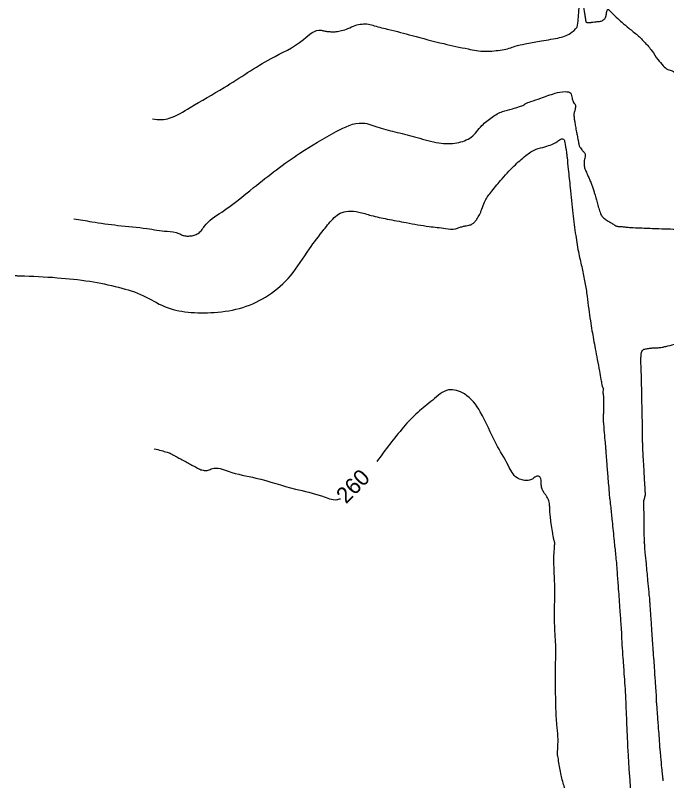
# Model space of a CAD drawing. Extents: x -475575 to -473225, y -1116053 to -1114104.
# Drawn here: x -475562.3 to -475400.4, y -1115778.9 to -1115588.6 of the extents above; entities that cross this region are included whole.
import ezdxf

# ---------------------------------------------------------------- set-up
doc = ezdxf.new("R2010")
doc.units = 0
for name, color, linetype in [('Vrstevnice_hlavni', 7, 'Continuous'), ('Vrstevnice_popis', 7, 'Continuous'), ('Vrstevnice_vedlejsi', 7, 'Continuous')]:
    doc.layers.add(name, color=color, linetype=linetype)

msp = doc.modelspace()

# ---------------------------------------------------------------- linework, layer by layer
at = {"layer": 'Vrstevnice_hlavni'}
for points in [[(-475427.48600000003, -1115772.132), (-475427.49100000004, -1115772.047), (-475427.47500000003, -1115771.565), (-475427.43600000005, -1115770.685), (-475427.37600000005, -1115769.409), (-475427.39, -1115768.06), (-475427.48000000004, -1115766.6400000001), (-475427.645, -1115765.148), (-475427.76700000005, -1115763.73), (-475427.847, -1115762.387), (-475427.884, -1115761.118), (-475427.927, -1115759.2580000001), (-475427.978, -1115756.807), (-475428.03400000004, -1115753.7650000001), (-475428.041, -1115751.345), (-475427.99600000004, -1115749.547), (-475427.901, -1115748.371), (-475427.895, -1115746.679), (-475427.977, -1115744.47), (-475428.14900000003, -1115741.745), (-475428.24100000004, -1115739.05), (-475428.25200000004, -1115736.386), (-475428.184, -1115733.7510000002), (-475428.178, -1115731.1800000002), (-475428.234, -1115728.672), (-475428.353, -1115726.2280000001), (-475428.39300000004, -1115724.148), (-475428.35500000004, -1115722.4340000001), (-475428.24000000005, -1115721.083), (-475428.199, -1115720.101), (-475428.233, -1115719.4880000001), (-475428.342, -1115719.242), (-475428.51700000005, -1115718.399), (-475428.759, -1115716.959), (-475429.06700000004, -1115714.922), (-475429.283, -1115713.216), (-475429.408, -1115711.841), (-475429.44100000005, -1115710.798), (-475429.52400000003, -1115709.952), (-475429.657, -1115709.3050000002), (-475429.83900000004, -1115708.855), (-475430.12700000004, -1115708.324), (-475430.521, -1115707.712), (-475431.021, -1115707.017), (-475431.37200000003, -1115706.139), (-475431.574, -1115705.077), (-475431.628, -1115703.831), (-475432.03900000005, -1115703.232), (-475432.808, -1115703.28), (-475433.934, -1115703.976), (-475435.102, -1115704.2580000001), (-475436.31200000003, -1115704.127), (-475437.563, -1115703.583), (-475439.711, -1115700.578), (-475442.75700000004, -1115695.111), (-475446.7, -1115687.183), (-475450.641, -1115682.727), (-475454.581, -1115681.744), (-475458.52, -1115684.232), (-475462.25200000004, -1115687.314), (-475465.77800000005, -1115690.989), (-475472.417, -1115699.5250000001)], [(-475527.74600000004, -1115696.3490000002), (-475525.965, -1115696.8020000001), (-475524.571, -1115697.22), (-475523.56600000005, -1115697.601), (-475522.949, -1115697.946), (-475522.123, -1115698.398), (-475521.08900000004, -1115698.9570000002), (-475519.847, -1115699.6230000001), (-475518.65300000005, -1115700.264), (-475517.50700000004, -1115700.879), (-475516.41000000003, -1115701.468), (-475515.34400000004, -1115701.734), (-475514.309, -1115701.6770000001), (-475513.304, -1115701.2950000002), (-475509.358, -1115701.952), (-475502.46900000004, -1115703.646), (-475492.639, -1115706.378), (-475485.938, -1115708.164), (-475482.367, -1115709.002), (-475481.483, -1115708.786)], [(-475432.54600000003, -1115864.7240000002), (-475432.438, -1115866.5180000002), (-475432.42000000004, -1115867.2), (-475432.43600000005, -1115867.668), (-475432.488, -1115867.922), (-475432.49700000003, -1115868.151), (-475432.465, -1115868.355), (-475432.391, -1115868.534), (-475432.05500000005, -1115868.639), (-475431.456, -1115868.671), (-475430.59500000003, -1115868.629), (-475429.677, -1115868.433), (-475428.70200000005, -1115868.084), (-475427.67000000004, -1115867.581), (-475426.97000000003, -1115867.2380000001), (-475426.602, -1115867.057), (-475426.56600000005, -1115867.0350000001), (-475426.31600000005, -1115866.919), (-475425.85400000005, -1115866.706), (-475425.178, -1115866.398), (-475424.803, -1115865.685), (-475424.72900000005, -1115864.568), (-475424.955, -1115863.047), (-475424.634, -1115861.753), (-475423.764, -1115860.686), (-475422.34500000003, -1115859.8460000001), (-475421.254, -1115858.935), (-475420.49100000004, -1115857.9540000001), (-475420.05500000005, -1115856.9030000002), (-475419.68600000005, -1115856.084), (-475419.38200000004, -1115855.4980000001), (-475419.145, -1115855.1430000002), (-475418.961, -1115854.685), (-475418.831, -1115854.122), (-475418.755, -1115853.455), (-475418.75800000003, -1115851.736), (-475418.842, -1115848.962), (-475419.005, -1115845.136), (-475419.118, -1115842.469), (-475419.18000000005, -1115840.9610000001), (-475419.193, -1115840.612), (-475419.22900000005, -1115840.026), (-475419.291, -1115839.203), (-475419.37600000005, -1115838.142), (-475419.465, -1115836.504), (-475419.558, -1115834.288), (-475419.655, -1115831.494), (-475419.75, -1115829.593), (-475419.846, -1115828.587), (-475419.94, -1115828.4740000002), (-475420.16500000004, -1115827.6430000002), (-475420.522, -1115826.095), (-475421.01, -1115823.827), (-475421.44700000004, -1115821.397), (-475421.83400000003, -1115818.8020000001), (-475422.17100000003, -1115816.043), (-475422.433, -1115813.953), (-475422.62, -1115812.529), (-475422.732, -1115811.774), (-475422.786, -1115811.155), (-475422.781, -1115810.672), (-475422.71800000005, -1115810.3260000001), (-475422.907, -1115809.202), (-475423.34900000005, -1115807.299), (-475424.044, -1115804.619), (-475424.51300000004, -1115802.821), (-475424.756, -1115801.905), (-475424.77300000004, -1115801.872), (-475424.776, -1115801.469), (-475424.76300000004, -1115800.698), (-475424.737, -1115799.557), (-475424.70800000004, -1115798.28), (-475424.678, -1115796.867), (-475424.647, -1115795.318), (-475424.635, -1115793.85), (-475424.64400000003, -1115792.463), (-475424.673, -1115791.158), (-475424.722, -1115789.6060000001), (-475424.79000000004, -1115787.807), (-475424.879, -1115785.761), (-475424.95800000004, -1115784.2410000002), (-475425.027, -1115783.247), (-475425.087, -1115782.779), (-475425.14, -1115782.441), (-475425.185, -1115782.234), (-475425.22400000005, -1115782.1570000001), (-475425.408, -1115781.607), (-475425.738, -1115780.5860000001), (-475426.21400000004, -1115779.092), (-475426.62, -1115777.5010000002), (-475426.956, -1115775.813), (-475427.222, -1115774.0280000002), (-475427.39900000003, -1115772.8360000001), (-475427.48600000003, -1115772.235), (-475427.483, -1115772.226), (-475427.483, -1115772.192), (-475427.48600000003, -1115772.132)]]:
    msp.add_spline(points, degree=3, dxfattribs=at)
at = {"layer": 'Vrstevnice_vedlejsi'}
for points in [[(-475422.59400000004, -1115591.47), (-475422.356, -1115589.511), (-475422.178, -1115587.384), (-475422.06200000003, -1115585.0890000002), (-475422.006, -1115582.625), (-475421.824, -1115581.962), (-475421.514, -1115583.1), (-475421.07800000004, -1115586.04), (-475420.77300000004, -1115588.0860000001), (-475420.59900000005, -1115589.2410000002), (-475420.55600000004, -1115589.504), (-475420.521, -1115589.732), (-475420.494, -1115589.9270000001), (-475420.473, -1115590.087), (-475420.43700000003, -1115590.202), (-475420.385, -1115590.271), (-475420.318, -1115590.2950000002), (-475420.16000000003, -1115590.313), (-475419.91400000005, -1115590.327), (-475419.57800000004, -1115590.335), (-475419.331, -1115590.331), (-475419.174, -1115590.314), (-475419.106, -1115590.2850000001), (-475418.69200000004, -1115590.23), (-475417.934, -1115590.149), (-475416.83, -1115590.0420000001), (-475416.03400000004, -1115589.681), (-475415.54600000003, -1115589.065), (-475415.36500000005, -1115588.193), (-475415.215, -1115587.574), (-475415.09500000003, -1115587.2070000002), (-475415.005, -1115587.091), (-475414.608, -1115587.357), (-475413.902, -1115588.003), (-475412.88800000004, -1115589.03), (-475411.506, -1115590.289), (-475409.756, -1115591.78), (-475407.63800000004, -1115593.503), (-475405.73500000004, -1115595.372), (-475404.04600000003, -1115597.384), (-475402.571, -1115599.5420000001), (-475401.24100000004, -1115601.088), (-475400.054, -1115602.024), (-475399.011, -1115602.348), (-475397.672, -1115603.344), (-475396.037, -1115605.011), (-475394.107, -1115607.351), (-475392.14800000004, -1115609.598), (-475390.16000000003, -1115611.752), (-475388.145, -1115613.814), (-475386.76, -1115615.574), (-475386.006, -1115617.033), (-475385.884, -1115618.19), (-475385.238, -1115619.1160000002), (-475384.068, -1115619.811), (-475382.375, -1115620.276), (-475380.439, -1115621.279), (-475378.26200000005, -1115622.82), (-475375.84300000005, -1115624.9000000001), (-475373.658, -1115626.291), (-475371.70800000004, -1115626.995), (-475369.992, -1115627.01), (-475368.27, -1115626.7680000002), (-475366.544, -1115626.266), (-475364.81200000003, -1115625.506), (-475363.342, -1115625.334), (-475362.135, -1115625.7480000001), (-475361.19100000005, -1115626.749), (-475360.489, -1115627.4440000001), (-475360.02800000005, -1115627.831), (-475359.809, -1115627.911), (-475359.51800000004, -1115627.955), (-475359.15300000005, -1115627.963), (-475358.716, -1115627.935), (-475358.223, -1115627.602), (-475357.674, -1115626.963), (-475357.068, -1115626.019), (-475356.50200000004, -1115625.144), (-475355.97500000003, -1115624.3390000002), (-475355.488, -1115623.602), (-475354.933, -1115623.111), (-475354.31, -1115622.867), (-475353.619, -1115622.869), (-475352.982, -1115622.911), (-475352.39800000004, -1115622.9910000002), (-475351.869, -1115623.111), (-475351.357, -1115623.2280000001), (-475350.86500000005, -1115623.342), (-475350.391, -1115623.452), (-475349.90300000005, -1115623.344), (-475349.402, -1115623.0180000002), (-475348.88700000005, -1115622.4740000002), (-475348.325, -1115622.057), (-475347.71400000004, -1115621.7680000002), (-475347.05500000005, -1115621.6060000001), (-475345.527, -1115620.777), (-475343.131, -1115619.281)], [(-475528.15173670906, -1115614.3358564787), (-475525.906, -1115614.49), (-475523.99600000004, -1115614.136), (-475518.82200000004, -1115611.487), (-475510.384, -1115606.5420000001), (-475498.68100000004, -1115599.3), (-475490.629, -1115594.539), (-475486.226, -1115592.256), (-475485.47400000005, -1115592.453), (-475484.60500000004, -1115592.58), (-475483.62100000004, -1115592.637), (-475482.52, -1115592.6230000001), (-475481.18200000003, -1115592.361), (-475479.60500000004, -1115591.851), (-475477.78900000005, -1115591.092), (-475476.08900000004, -1115590.72), (-475474.505, -1115590.735), (-475473.036, -1115591.136), (-475469.422, -1115592.0820000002), (-475463.66400000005, -1115593.573), (-475455.76, -1115595.609), (-475449.722, -1115596.923), (-475445.549, -1115597.5150000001), (-475443.243, -1115597.385), (-475441.22400000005, -1115597.132), (-475439.492, -1115596.757), (-475438.049, -1115596.2580000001), (-475435.55700000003, -1115595.6670000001), (-475432.015, -1115594.983), (-475427.423, -1115594.206), (-475424.283, -1115593.0350000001), (-475422.59400000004, -1115591.47)], [(-475547.69399277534, -1115639.1499769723), (-475543.27800000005, -1115639.8900000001), (-475536.754, -1115640.798), (-475529.574, -1115641.5960000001), (-475524.521, -1115642.264), (-475521.596, -1115642.804), (-475520.798, -1115643.215), (-475519.9, -1115643.426), (-475518.90300000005, -1115643.438), (-475517.80600000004, -1115643.249), (-475516.836, -1115642.783), (-475515.993, -1115642.04), (-475515.277, -1115641.02), (-475510.95900000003, -1115637.477), (-475503.04000000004, -1115631.4100000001), (-475491.52, -1115622.82), (-475482.48600000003, -1115617.466), (-475475.93700000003, -1115615.348), (-475471.875, -1115616.466), (-475467.362, -1115617.665), (-475462.4, -1115618.945), (-475456.988, -1115620.3050000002), (-475452.504, -1115620.267), (-475448.94700000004, -1115618.83), (-475446.31700000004, -1115615.995), (-475443.734, -1115613.878), (-475441.19800000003, -1115612.48), (-475438.70800000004, -1115611.8), (-475436.939, -1115611.26), (-475435.88800000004, -1115610.862), (-475435.558, -1115610.604), (-475434.14800000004, -1115610.0320000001), (-475431.658, -1115609.147), (-475428.09, -1115607.949), (-475425.60500000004, -1115607.546), (-475424.205, -1115607.939), (-475423.88800000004, -1115609.128), (-475423.612, -1115609.968), (-475423.37700000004, -1115610.46), (-475423.183, -1115610.6030000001), (-475423.07, -1115610.865), (-475423.038, -1115611.247), (-475423.087, -1115611.747), (-475423.157, -1115612.1530000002), (-475423.24700000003, -1115612.465), (-475423.358, -1115612.683), (-475423.41400000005, -1115613.039), (-475423.41500000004, -1115613.5320000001), (-475423.363, -1115614.162), (-475423.239, -1115615.0520000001), (-475423.04500000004, -1115616.199), (-475422.78, -1115617.6060000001), (-475422.575, -1115618.6700000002), (-475422.43000000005, -1115619.392), (-475422.34500000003, -1115619.771), (-475422.287, -1115620.063), (-475422.255, -1115620.266), (-475422.25, -1115620.381), (-475422.216, -1115620.566), (-475422.15300000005, -1115620.82), (-475422.06100000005, -1115621.145), (-475421.825, -1115621.548), (-475421.445, -1115622.0320000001), (-475420.92100000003, -1115622.595), (-475420.636, -1115623.1700000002), (-475420.591, -1115623.757)], [(-475562.2764963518, -1115653.3017374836), (-475561.17000000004, -1115653.327), (-475551.87200000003, -1115653.81), (-475543.744, -1115654.713), (-475536.591, -1115656.209), (-475530.411, -1115658.298), (-475525.206, -1115660.98), (-475519.35000000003, -1115662.357), (-475512.84300000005, -1115662.4300000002), (-475505.68700000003, -1115661.199), (-475499.357, -1115658.1600000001), (-475493.856, -1115653.3120000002), (-475489.18200000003, -1115646.656), (-475485.565, -1115641.845), (-475483.005, -1115638.8800000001), (-475481.503, -1115637.759), (-475479.472, -1115637.2950000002), (-475476.91500000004, -1115637.4880000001), (-475473.83, -1115638.337), (-475469.886, -1115639.217), (-475465.08400000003, -1115640.127), (-475459.424, -1115641.068), (-475455.34500000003, -1115641.584), (-475452.84900000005, -1115641.675), (-475451.934, -1115641.342), (-475451.06200000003, -1115641.0790000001), (-475450.233, -1115640.886), (-475449.44800000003, -1115640.7650000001), (-475448.733, -1115640.449), (-475448.09, -1115639.94), (-475447.51900000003, -1115639.237), (-475446.923, -1115638.181), (-475446.30100000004, -1115636.774), (-475445.65400000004, -1115635.0150000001), (-475444.109, -1115632.641), (-475441.66400000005, -1115629.652), (-475438.32, -1115626.047), (-475435.367, -1115623.446), (-475432.804, -1115621.848), (-475430.631, -1115621.2550000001), (-475428.912, -1115620.6530000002), (-475427.647, -1115620.043), (-475426.835, -1115619.425), (-475426.238, -1115619.261), (-475425.857, -1115619.551), (-475425.69100000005, -1115620.296), (-475425.57800000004, -1115620.842), (-475425.51800000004, -1115621.19), (-475425.511, -1115621.3390000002), (-475425.49000000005, -1115621.4780000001), (-475425.45300000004, -1115621.605), (-475425.401, -1115621.7210000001), (-475425.329, -1115622.1500000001), (-475425.239, -1115622.892), (-475425.13, -1115623.9470000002), (-475424.837, -1115626.793), (-475424.359, -1115631.431), (-475423.69700000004, -1115637.86), (-475422.98000000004, -1115643.351), (-475422.20900000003, -1115647.905), (-475421.38300000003, -1115651.522), (-475420.69700000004, -1115655.016), (-475420.15, -1115658.388), (-475419.743, -1115661.638), (-475419.34, -1115664.5150000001), (-475418.94200000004, -1115667.019)], [(-475420.591, -1115623.757), (-475420.78400000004, -1115624.355), (-475420.89400000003, -1115624.931), (-475420.919, -1115625.482), (-475420.86000000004, -1115626.01), (-475420.761, -1115626.489), (-475420.62100000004, -1115626.919), (-475420.44200000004, -1115627.3), (-475420.185, -1115627.87), (-475419.852, -1115628.631), (-475419.443, -1115629.581), (-475419.068, -1115630.533), (-475418.726, -1115631.485), (-475418.419, -1115632.438), (-475418.168, -1115633.254), (-475417.97400000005, -1115633.9340000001), (-475417.837, -1115634.4780000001), (-475417.67100000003, -1115635.093), (-475417.476, -1115635.781), (-475417.25100000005, -1115636.541), (-475417.026, -1115637.223), (-475416.80000000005, -1115637.827), (-475416.575, -1115638.3530000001), (-475416.036, -1115638.938), (-475415.18600000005, -1115639.581), (-475414.022, -1115640.283), (-475413.22900000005, -1115640.7580000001), (-475412.80700000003, -1115641.0050000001), (-475412.755, -1115641.024), (-475412.63, -1115641.037), (-475412.43100000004, -1115641.044), (-475412.16000000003, -1115641.0450000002), (-475411.829, -1115641.064), (-475411.44, -1115641.102), (-475410.99100000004, -1115641.1600000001), (-475410.482, -1115641.217), (-475409.913, -1115641.274), (-475409.28400000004, -1115641.33), (-475406.977, -1115641.435), (-475402.993, -1115641.59), (-475397.332, -1115641.793), (-475393.489, -1115641.9610000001), (-475391.46300000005, -1115642.094), (-475391.256, -1115642.191), (-475390.696, -1115642.102), (-475389.783, -1115641.828), (-475388.51700000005, -1115641.368), (-475387.42000000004, -1115641.034), (-475386.489, -1115640.825), (-475385.727, -1115640.7410000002), (-475382.67100000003, -1115640.855), (-475377.321, -1115641.1670000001), (-475369.677, -1115641.676), (-475364.31100000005, -1115642.119), (-475361.221, -1115642.494), (-475360.40900000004, -1115642.803), (-475359.049, -1115642.79), (-475357.14, -1115642.4570000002), (-475354.684, -1115641.8020000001), (-475351.81100000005, -1115641.3050000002), (-475348.521, -1115640.965), (-475344.814, -1115640.783), (-475341.787, -1115640.733), (-475339.44, -1115640.817), (-475337.772, -1115641.034), (-475336.47000000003, -1115641.043), (-475335.533, -1115640.844), (-475334.961, -1115640.438), (-475334.483, -1115640.144), (-475334.10000000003, -1115639.963), (-475333.81100000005, -1115639.8930000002), (-475333.494, -1115639.811), (-475333.14900000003, -1115639.716), (-475332.776, -1115639.609), (-475331.672, -1115639.0620000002), (-475329.83900000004, -1115638.0760000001), (-475327.27400000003, -1115636.651), (-475324.21, -1115635.225), (-475320.646, -1115633.797), (-475316.581, -1115632.368), (-475311.852, -1115630.912), (-475306.457, -1115629.431), (-475300.397, -1115627.924), (-475296.09300000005, -1115626.3460000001), (-475293.543, -1115624.6970000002), (-475292.748, -1115622.976), (-475292.068, -1115621.749), (-475291.503, -1115621.014), (-475291.053, -1115620.772), (-475290.15, -1115620.479), (-475288.793, -1115620.1330000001), (-475286.982, -1115619.736), (-475285.55500000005, -1115619.4880000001), (-475284.511, -1115619.388), (-475283.85000000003, -1115619.436), (-475282.88200000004, -1115619.31), (-475281.607, -1115619.009)], [(-475405.97500000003, -1115709.014), (-475405.91000000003, -1115708.871), (-475405.863, -1115708.736), (-475405.83300000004, -1115708.609), (-475405.821, -1115708.49), (-475405.797, -1115708.3560000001), (-475405.75800000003, -1115708.206), (-475405.707, -1115708.0420000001), (-475405.673, -1115707.895), (-475405.65400000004, -1115707.7650000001), (-475405.652, -1115707.6530000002), (-475405.716, -1115706.45), (-475405.84500000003, -1115704.156), (-475406.04000000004, -1115700.773), (-475406.18000000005, -1115698.348), (-475406.26700000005, -1115696.884), (-475406.30000000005, -1115696.379), (-475406.32300000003, -1115695.6530000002), (-475406.337, -1115694.708), (-475406.34, -1115693.543), (-475406.36600000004, -1115691.762), (-475406.412, -1115689.364), (-475406.48000000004, -1115686.351), (-475406.53500000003, -1115683.749), (-475406.57800000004, -1115681.5590000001), (-475406.608, -1115679.78), (-475406.64900000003, -1115678.147), (-475406.701, -1115676.659), (-475406.764, -1115675.315), (-475406.771, -1115674.1670000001), (-475406.72400000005, -1115673.2140000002), (-475406.62100000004, -1115672.455), (-475406.397, -1115671.923), (-475406.052, -1115671.617), (-475405.587, -1115671.537), (-475405.119, -1115671.4570000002), (-475404.64900000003, -1115671.379), (-475404.17600000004, -1115671.301), (-475403.71300000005, -1115671.256), (-475403.25800000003, -1115671.242), (-475402.81100000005, -1115671.26), (-475402.21900000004, -1115671.2110000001), (-475401.48000000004, -1115671.0960000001), (-475400.596, -1115670.913), (-475398.428, -1115670.3760000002), (-475394.978, -1115669.485), (-475390.244, -1115668.2410000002), (-475385.281, -1115666.7550000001), (-475380.087, -1115665.027), (-475374.66500000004, -1115663.056), (-475370.26300000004, -1115661.656), (-475366.88300000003, -1115660.827), (-475364.52400000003, -1115660.568), (-475362.397, -1115660.674), (-475360.50200000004, -1115661.145), (-475358.83800000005, -1115661.982), (-475355.413, -1115661.9610000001), (-475350.226, -1115661.085), (-475343.27800000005, -1115659.352), (-475338.564, -1115658.164), (-475336.08400000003, -1115657.522), (-475335.83900000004, -1115657.425), (-475335.607, -1115657.443), (-475335.389, -1115657.5760000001), (-475335.185, -1115657.823), (-475334.88, -1115657.7210000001), (-475334.47400000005, -1115657.269), (-475333.96800000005, -1115656.468), (-475333.36500000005, -1115655.745), (-475332.666, -1115655.102), (-475331.87, -1115654.537), (-475331.33800000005, -1115654.1600000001), (-475331.068, -1115653.9710000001), (-475331.06100000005, -1115653.969), (-475331.053, -1115653.967), (-475331.04500000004, -1115653.965), (-475331.036, -1115653.962), (-475330.955, -1115653.919), (-475330.802, -1115653.835), (-475330.57700000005, -1115653.71), (-475330.30100000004, -1115653.733), (-475329.97400000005, -1115653.905), (-475329.59500000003, -1115654.225), (-475329.101, -1115655.023), (-475328.493, -1115656.3), (-475327.77, -1115658.0550000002), (-475326.455, -1115659.105), (-475324.549, -1115659.449), (-475322.05100000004, -1115659.088), (-475320.233, -1115658.591), (-475319.09500000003, -1115657.956), (-475318.636, -1115657.1840000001), (-475317.511, -1115656.333), (-475315.71800000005, -1115655.402), (-475313.259, -1115654.391), (-475311.10400000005, -1115653.399), (-475309.25100000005, -1115652.426)], [(-475418.94200000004, -1115667.019), (-475418.548, -1115669.151), (-475418.107, -1115671.537), (-475417.618, -1115674.178), (-475417.081, -1115677.073), (-475416.701, -1115679.132), (-475416.477, -1115680.3530000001), (-475416.40900000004, -1115680.737), (-475416.34400000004, -1115680.995), (-475416.282, -1115681.127), (-475416.223, -1115681.135), (-475416.168, -1115681.745), (-475416.117, -1115682.958), (-475416.07, -1115684.774), (-475416.052, -1115686.149), (-475416.065, -1115687.083), (-475416.107, -1115687.575), (-475416.13800000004, -1115688.026), (-475416.15900000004, -1115688.435), (-475416.169, -1115688.8020000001), (-475416.10000000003, -1115689.896), (-475415.95200000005, -1115691.718), (-475415.726, -1115694.266), (-475415.568, -1115696.0860000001), (-475415.478, -1115697.178), (-475415.456, -1115697.541), (-475415.35000000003, -1115698.932), (-475415.16000000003, -1115701.351), (-475414.885, -1115704.799), (-475414.68200000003, -1115707.234), (-475414.55100000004, -1115708.6570000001), (-475414.492, -1115709.067), (-475414.28500000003, -1115710.9740000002), (-475413.93000000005, -1115714.3760000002), (-475413.427, -1115719.2750000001), (-475413.076, -1115722.7380000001), (-475412.87600000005, -1115724.766), (-475412.82800000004, -1115725.359), (-475412.668, -1115727.516), (-475412.39400000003, -1115731.2380000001), (-475412.009, -1115736.5250000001), (-475411.74600000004, -1115740.279), (-475411.607, -1115742.5), (-475411.591, -1115743.188), (-475411.47500000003, -1115745.165), (-475411.25700000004, -1115748.4300000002), (-475410.939, -1115752.985), (-475410.721, -1115756.1430000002), (-475410.60400000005, -1115757.906), (-475410.58800000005, -1115758.274), (-475410.515, -1115760.0820000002), (-475410.384, -1115763.331), (-475410.196, -1115768.021), (-475409.98000000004, -1115772.34), (-475409.737, -1115776.289), (-475409.466, -1115779.867), (-475409.28, -1115782.5150000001), (-475409.177, -1115784.232), (-475409.15900000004, -1115785.0180000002), (-475408.99100000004, -1115787.0590000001), (-475408.672, -1115790.355), (-475408.20300000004, -1115794.9070000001), (-475407.87, -1115798.117), (-475407.67500000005, -1115799.987), (-475407.617, -1115800.516), (-475407.51, -1115801.959), (-475407.35500000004, -1115804.317), (-475407.151, -1115807.5890000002), (-475407.004, -1115809.9570000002), (-475406.91400000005, -1115811.421), (-475406.88, -1115811.98), (-475406.78400000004, -1115813.425), (-475406.624, -1115815.757), (-475406.401, -1115818.975), (-475406.291, -1115821.199), (-475406.292, -1115822.431), (-475406.405, -1115822.6700000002), (-475406.353, -1115823.94), (-475406.135, -1115826.24), (-475405.75100000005, -1115829.5720000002), (-475405.48500000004, -1115831.931), (-475405.335, -1115833.318), (-475405.30100000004, -1115833.733), (-475405.238, -1115835.1500000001), (-475405.146, -1115837.568), (-475405.025, -1115840.989), (-475404.94, -1115843.365), (-475404.891, -1115844.6970000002), (-475404.879, -1115844.985), (-475404.726, -1115845.997), (-475404.433, -1115847.735), (-475403.999, -1115850.199), (-475403.63200000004, -1115852.715), (-475403.33400000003, -1115855.286), (-475403.102, -1115857.9100000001), (-475402.951, -1115859.686), (-475402.88, -1115860.614)], [(-475401.211, -1115778.911), (-475401.223, -1115778.8020000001), (-475401.238, -1115778.691), (-475401.25700000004, -1115778.5790000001), (-475401.27800000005, -1115778.465), (-475401.378, -1115777.5), (-475401.55600000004, -1115775.682), (-475401.81200000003, -1115773.013), (-475401.987, -1115771.195), (-475402.081, -1115770.226), (-475402.09400000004, -1115770.108), (-475402.10000000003, -1115769.986), (-475402.098, -1115769.86), (-475402.09, -1115769.729), (-475402.085, -1115769.6330000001), (-475402.085, -1115769.5690000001), (-475402.08900000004, -1115769.54), (-475402.18200000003, -1115768.34), (-475402.364, -1115765.9710000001), (-475402.634, -1115762.432), (-475402.814, -1115760.05), (-475402.902, -1115758.8260000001), (-475402.9, -1115758.76), (-475402.9, -1115758.69), (-475402.90300000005, -1115758.6160000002), (-475402.90900000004, -1115758.538), (-475402.91400000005, -1115758.465), (-475402.918, -1115758.397), (-475402.92100000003, -1115758.334), (-475402.922, -1115758.274), (-475402.922, -1115758.216), (-475402.92000000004, -1115758.1600000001), (-475402.91400000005, -1115758.101), (-475402.905, -1115758.04), (-475402.89300000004, -1115757.976), (-475402.889, -1115757.892), (-475402.89300000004, -1115757.789), (-475402.905, -1115757.666), (-475402.992, -1115756.452), (-475403.155, -1115754.145), (-475403.39300000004, -1115750.747), (-475403.55000000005, -1115748.452), (-475403.62700000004, -1115747.26), (-475403.624, -1115747.171), (-475403.62600000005, -1115747.084), (-475403.63300000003, -1115747.0010000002), (-475403.647, -1115746.9200000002), (-475403.66000000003, -1115746.8460000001), (-475403.67100000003, -1115746.78), (-475403.68200000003, -1115746.7210000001), (-475403.69200000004, -1115746.634), (-475403.7, -1115746.519), (-475403.707, -1115746.375), (-475403.715, -1115746.246), (-475403.72400000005, -1115746.132), (-475403.73500000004, -1115746.033), (-475403.824, -1115744.737), (-475403.993, -1115742.245), (-475404.24000000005, -1115738.557), (-475404.411, -1115736.0280000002), (-475404.506, -1115734.659), (-475404.52400000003, -1115734.448), (-475404.53400000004, -1115734.271), (-475404.53400000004, -1115734.1260000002), (-475404.526, -1115734.014), (-475404.52400000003, -1115733.919), (-475404.52900000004, -1115733.84), (-475404.54000000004, -1115733.7780000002), (-475404.55500000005, -1115733.69), (-475404.574, -1115733.5760000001), (-475404.596, -1115733.438), (-475404.742, -1115731.956), (-475405.014, -1115729.1300000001), (-475405.411, -1115724.9610000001), (-475405.677, -1115722.128), (-475405.81200000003, -1115720.6300000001), (-475405.81600000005, -1115720.467), (-475405.819, -1115720.334), (-475405.821, -1115720.229), (-475405.821, -1115720.154), (-475405.83300000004, -1115720.0620000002), (-475405.857, -1115719.9540000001), (-475405.89300000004, -1115719.8290000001), (-475405.916, -1115719.727), (-475405.92500000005, -1115719.647), (-475405.922, -1115719.59), (-475405.918, -1115719.512), (-475405.91500000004, -1115719.413), (-475405.912, -1115719.294), (-475405.923, -1115718.1260000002), (-475405.949, -1115715.911), (-475405.99000000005, -1115712.648), (-475406.01800000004, -1115710.4470000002), (-475406.033, -1115709.3090000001), (-475406.037, -1115709.233), (-475406.01700000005, -1115709.135), (-475405.97500000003, -1115709.014)]]:
    msp.add_spline(points, degree=3, dxfattribs=at)

# ---------------------------------------------------------------- texts
at = {"layer": 'Vrstevnice_popis'}
msp.add_text(' 260 ', height=4, rotation=45.76428485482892, dxfattribs=at).set_placement((-475481.0815203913, -1115711.3023916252))

doc.saveas('drawing.dxf')
